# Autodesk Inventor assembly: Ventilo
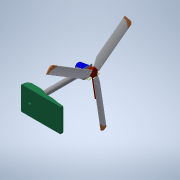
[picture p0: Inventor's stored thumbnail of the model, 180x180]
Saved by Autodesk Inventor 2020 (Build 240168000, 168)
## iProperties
Created: 2013-01
Part Number: Ventilo
Document SubType Name: Assembly
Designer: Bruno
Author: Bruno
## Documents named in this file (3)
- C:\Users\bruno\Documents\1-Cours-2021-22\Cours\Mécanique\Cinématique\2-Cinématique-V=W.R-Ventilo\ventilo-Inventor\Ventilo.iam
- C:\Users\bruno\Documents\1-Cours-2021-22\Cours\Mécanique\Cinématique\2-Cinématique-V=W.R-Ventilo\ventilo-Inventor\Ventilo-base.iam
- C:\Users\bruno\Documents\1-Cours-2021-22\Cours\Mécanique\Cinématique\2-Cinématique-V=W.R-Ventilo\ventilo-Inventor\Hélice.iam
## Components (2 placed, 2 different names)
1. Ventilo-base:1 [sub-assembly] — Placage:1, Affleurement:1
2. Hélice:1 [sub-assembly] — Placage:1, Affleurement:1
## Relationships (2: Mate 1, Flush 1)
- Placage:1 [Mate]: Ventilo-base:1 ↔ Hélice:1
- Affleurement:1 [Flush]: Ventilo-base:1 ↔ Hélice:1
